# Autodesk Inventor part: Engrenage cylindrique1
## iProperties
Created: 2011-10
Part Number: Engrenage cylindrique1
Material: Steel
Document SubType Name: Modeling
Designer: Laur
Density: 1 g/cm^3
CustomPartVersion: 1
Author: Laur
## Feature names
1. Extrusion1
2. Extrusion2
